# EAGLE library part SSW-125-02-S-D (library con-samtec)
THROUGH-HOLE .025" SQ POST SOCKET Source: Samtec SSW.pdf
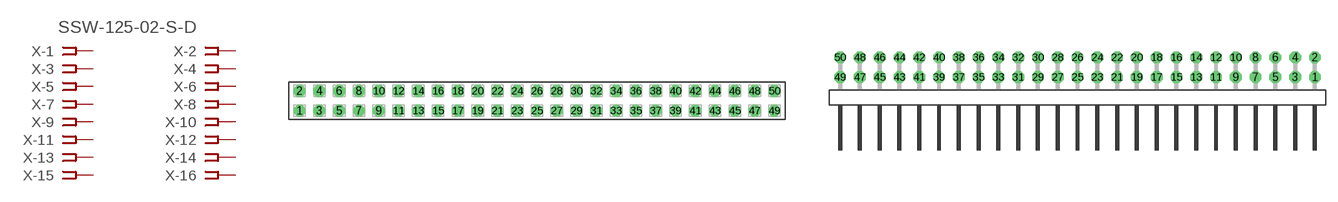
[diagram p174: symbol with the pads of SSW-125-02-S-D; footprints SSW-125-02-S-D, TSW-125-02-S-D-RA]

Designator prefix X; gates -1=FPINV -2=FPIN -3=FPIN -4=FPIN -5=FPIN -6=FPIN -7=FPIN -8=FPIN -9=FPIN -10=FPIN -11=FPIN -12=FPIN -13=FPIN -14=FPIN -15=FPIN -16=FPIN -17=FPIN -18=FPIN -19=FPIN -20=FPIN -21=FPIN -22=FPIN -23=FPIN -24=FPIN -25=FPIN -26=FPIN -27=FPIN -28=FPIN -29=FPIN -30=FPIN -31=FPIN -32=FPIN -33=FPIN -34=FPIN -35=FPIN -36=FPIN -37=FPIN -38=FPIN -39=FPIN -40=FPIN -41=FPIN -42=FPIN -43=FPIN -44=FPIN -45=FPIN -46=FPIN -47=FPIN -48=FPIN -49=FPIN -50=FPIN

## SSW-125-02-S-D (MPN: SSW-125-02-S-D; OC_FARNELL: unknown; OC_NEWARK: 11P9723)  [SSW-125-02-S-D]
1  -1:1  pas
2  -2:1  pas
3  -3:1  pas
4  -4:1  pas
5  -5:1  pas
6  -6:1  pas
7  -7:1  pas
8  -8:1  pas
9  -9:1  pas
10  -10:1  pas
11  -11:1  pas
12  -12:1  pas
13  -13:1  pas
14  -14:1  pas
15  -15:1  pas
16  -16:1  pas
17  -17:1  pas
18  -18:1  pas
19  -19:1  pas
20  -20:1  pas
21  -21:1  pas
22  -22:1  pas
23  -23:1  pas
24  -24:1  pas
25  -25:1  pas
26  -26:1  pas
27  -27:1  pas
28  -28:1  pas
29  -29:1  pas
30  -30:1  pas
31  -31:1  pas
32  -32:1  pas
33  -33:1  pas
34  -34:1  pas
35  -35:1  pas
36  -36:1  pas
37  -37:1  pas
38  -38:1  pas
39  -39:1  pas
40  -40:1  pas
41  -41:1  pas
42  -42:1  pas
43  -43:1  pas
44  -44:1  pas
45  -45:1  pas
46  -46:1  pas
47  -47:1  pas
48  -48:1  pas
49  -49:1  pas
50  -50:1  pas

## SSW-125-02-S-D-RA (MPN: SSW-125-02-S-D-RA; OC_FARNELL: unknown; OC_NEWARK: 11P9724)  [TSW-125-02-S-D-RA]
Pads as for SSW-125-02-S-D

## Footprint SSW-125-02-S-D (pad centres in mm)
THROUGH-HOLE .025" SQ POST SOCKET Source: Samtec SSW.pdf
drill 1 pad 1.5 octagon: 1 -30.48,-1.27; 2 -30.48,1.27; 3 -27.94,-1.27; 4 -27.94,1.27; 5 -25.4,-1.27; 6 -25.4,1.27; 7 -22.86,-1.27; 8 -22.86,1.27; 9 -20.32,-1.27; 10 -20.32,1.27; 11 -17.78,-1.27; 12 -17.78,1.27; 13 -15.24,-1.27; 14 -15.24,1.27; 15 -12.7,-1.27; 16 -12.7,1.27; 17 -10.16,-1.27; 18 -10.16,1.27; 19 -7.62,-1.27; 20 -7.62,1.27; 21 -5.08,-1.27; 22 -5.08,1.27; 23 -2.54,-1.27; 24 -2.54,1.27; 25 0,-1.27; 26 0,1.27; 27 2.54,-1.27; 28 2.54,1.27; 29 5.08,-1.27; 30 5.08,1.27; 31 7.62,-1.27; 32 7.62,1.27; 33 10.16,-1.27; 34 10.16,1.27; 35 12.7,-1.27; 36 12.7,1.27; 37 15.24,-1.27; 38 15.24,1.27; 39 17.78,-1.27; 40 17.78,1.27; 41 20.32,-1.27; 42 20.32,1.27; 43 22.86,-1.27; 44 22.86,1.27; 45 25.4,-1.27; 46 25.4,1.27; 47 27.94,-1.27; 48 27.94,1.27; 49 30.48,-1.27; 50 30.48,1.27

## Footprint TSW-125-02-S-D-RA (pad centres in mm)
THROUGH-HOLE .025" SQ POST HEADER Source: Samtec TSW.pdf
drill 1 pad 1.5 octagon: 1 30.48,1.524; 2 30.48,4.064; 3 27.94,1.524; 4 27.94,4.064; 5 25.4,1.524; 6 25.4,4.064; 7 22.86,1.524; 8 22.86,4.064; 9 20.32,1.524; 10 20.32,4.064; 11 17.78,1.524; 12 17.78,4.064; 13 15.24,1.524; 14 15.24,4.064; 15 12.7,1.524; 16 12.7,4.064; 17 10.16,1.524; 18 10.16,4.064; 19 7.62,1.524; 20 7.62,4.064; 21 5.08,1.524; 22 5.08,4.064; 23 2.54,1.524; 24 2.54,4.064; 25 0,1.524; 26 0,4.064; 27 -2.54,1.524; 28 -2.54,4.064; 29 -5.08,1.524; 30 -5.08,4.064; 31 -7.62,1.524; 32 -7.62,4.064; 33 -10.16,1.524; 34 -10.16,4.064; 35 -12.7,1.524; 36 -12.7,4.064; 37 -15.24,1.524; 38 -15.24,4.064; 39 -17.78,1.524; 40 -17.78,4.064; 41 -20.32,1.524; 42 -20.32,4.064; 43 -22.86,1.524; 44 -22.86,4.064; 45 -25.4,1.524; 46 -25.4,4.064; 47 -27.94,1.524; 48 -27.94,4.064; 49 -30.48,1.524; 50 -30.48,4.064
